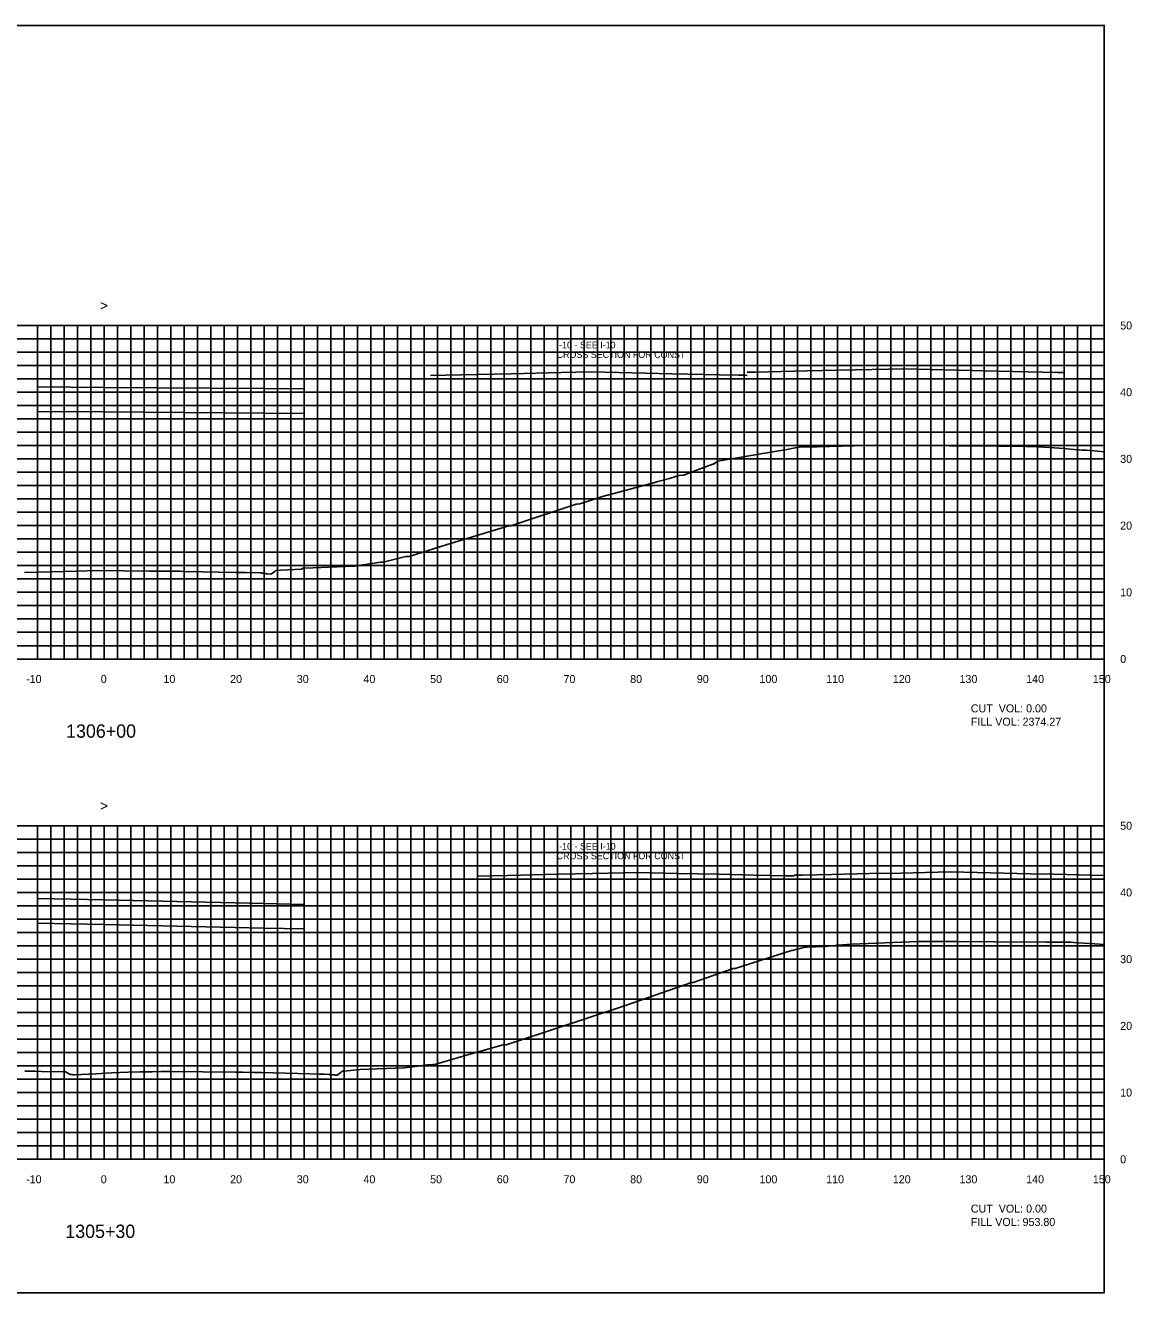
# Model space of a CAD drawing. Extents: x 1797714 to 1804825, y 249015 to 250269.
# Drawn here: x 1804319.2 to 1804485.1, y 250079.4 to 250269.4 of the extents above; entities that cross this region are included whole.
import ezdxf

# ---------------------------------------------------------------- set-up
doc = ezdxf.new("R2010")
doc.units = 0
for name, color, linetype in [('1', 7, 'Continuous'), ('10', 7, 'Continuous'), ('3', 7, 'Continuous'), ('31', 7, 'Continuous'), ('60', 7, 'Continuous'), ('ANNO-TXT', 7, 'Continuous'), ('BRG-DECK', 7, 'Continuous'), ('CL-CNST', 7, 'Continuous'), ('Level 62', 7, 'Continuous'), ('M-ROADS', 7, 'Continuous')]:
    doc.layers.add(name, color=color, linetype=linetype)

msp = doc.modelspace()

# ---------------------------------------------------------------- linework, layer by layer
msp.add_lwpolyline([(1804181, 250079.43), (1804481, 250079.43), (1804481, 250269.43), (1804181, 250269.43)], close=True)
at = {"layer": '60'}
for p, q in [((1804481, 250174.43), (1804481, 250224.43)), ((1804481.06, 250224.43), (1804481, 250224.43)), ((1804481.06, 250214.43), (1804481, 250214.43)), ((1804481.06, 250204.43), (1804481, 250204.43)), ((1804481.06, 250194.43), (1804481, 250194.43)), ((1804481.06, 250184.43), (1804481, 250184.43)), ((1804181, 250174.43), (1804481, 250174.43)), ((1804321, 250174.37), (1804321, 250174.43)), ((1804331, 250174.37), (1804331, 250174.43)), ((1804341, 250174.37), (1804341, 250174.43)), ((1804351, 250174.37), (1804351, 250174.43)), ((1804361, 250174.37), (1804361, 250174.43)), ((1804371, 250174.37), (1804371, 250174.43)), ((1804381, 250174.37), (1804381, 250174.43)), ((1804391, 250174.37), (1804391, 250174.43)), ((1804401, 250174.37), (1804401, 250174.43)), ((1804411, 250174.37), (1804411, 250174.43)), ((1804421, 250174.37), (1804421, 250174.43)), ((1804431, 250174.37), (1804431, 250174.43)), ((1804441, 250174.37), (1804441, 250174.43)), ((1804451, 250174.37), (1804451, 250174.43)), ((1804461, 250174.37), (1804461, 250174.43)), ((1804471, 250174.37), (1804471, 250174.43)), ((1804481, 250174.37), (1804481, 250174.43)), ((1804481.06, 250174.43), (1804481, 250174.43)), ((1804481, 250099.43), (1804481, 250149.43)), ((1804481.06, 250149.43), (1804481, 250149.43)), ((1804481.06, 250139.43), (1804481, 250139.43)), ((1804481.06, 250129.43), (1804481, 250129.43)), ((1804481.06, 250119.43), (1804481, 250119.43)), ((1804481.06, 250109.43), (1804481, 250109.43)), ((1804181, 250099.43), (1804481, 250099.43)), ((1804321, 250099.37), (1804321, 250099.43)), ((1804331, 250099.37), (1804331, 250099.43)), ((1804341, 250099.37), (1804341, 250099.43)), ((1804351, 250099.37), (1804351, 250099.43)), ((1804361, 250099.37), (1804361, 250099.43)), ((1804371, 250099.37), (1804371, 250099.43)), ((1804381, 250099.37), (1804381, 250099.43)), ((1804391, 250099.37), (1804391, 250099.43)), ((1804401, 250099.37), (1804401, 250099.43)), ((1804411, 250099.37), (1804411, 250099.43)), ((1804421, 250099.37), (1804421, 250099.43)), ((1804431, 250099.37), (1804431, 250099.43)), ((1804441, 250099.37), (1804441, 250099.43)), ((1804451, 250099.37), (1804451, 250099.43)), ((1804461, 250099.37), (1804461, 250099.43)), ((1804471, 250099.37), (1804471, 250099.43)), ((1804481, 250099.37), (1804481, 250099.43)), ((1804481.06, 250099.43), (1804481, 250099.43))]:
    msp.add_line(p, q, dxfattribs=at)
at = {"layer": 'BRG-DECK'}
for points in [[(1804361, 250211.25), (1804361, 250214.93), (1804355, 250214.97), (1804331, 250215.16), (1804321, 250215.23), (1804321, 250211.55), (1804331, 250211.48), (1804355, 250211.29)], [(1804361, 250133.97), (1804361, 250137.65), (1804355, 250137.78), (1804331, 250138.31), (1804321, 250138.53), (1804321, 250134.85), (1804331, 250134.63), (1804355, 250134.1)]]:
    msp.add_lwpolyline(points, close=True, dxfattribs=at)
at = {"layer": 'CL-CNST'}
for points in [[(1804379.96, 250216.94), (1804386.86, 250217.09), (1804392.02, 250217.21), (1804399.53, 250217.37), (1804404.08, 250217.47), (1804412.21, 250217.29), (1804416.15, 250217.21), (1804423.37, 250217.05), (1804426.2, 250216.99), (1804427.11, 250216.97), (1804427.45, 250216.96)], [(1804427.45, 250217.43), (1804427.78, 250217.44), (1804428.71, 250217.45), (1804436.46, 250217.62), (1804438.76, 250217.67), (1804448.65, 250217.88), (1804450.82, 250217.93), (1804461.32, 250217.69), (1804462.88, 250217.65), (1804474, 250217.4), (1804474.94, 250217.38)], [(1804321, 250215.23), (1804331, 250215.16), (1804355, 250214.97), (1804361, 250214.93)], [(1804387.03, 250141.89), (1804391.57, 250141.99), (1804399.09, 250142.15), (1804404.24, 250142.26), (1804411.15, 250142.41), (1804416.92, 250142.29), (1804423.21, 250142.15), (1804428.49, 250142.03), (1804433.26, 250141.92), (1804433.95, 250141.91), (1804434.51, 250141.9)], [(1804434.52, 250142), (1804435.08, 250142.02), (1804435.77, 250142.03), (1804440.08, 250142.12), (1804445.82, 250142.25), (1804450.49, 250142.34), (1804457.89, 250142.5), (1804461.99, 250142.41), (1804469.95, 250142.23), (1804473.5, 250142.15), (1804481, 250141.98)], [(1804321, 250138.53), (1804331, 250138.31), (1804355, 250137.78), (1804361, 250137.65)]]:
    msp.add_lwpolyline(points, dxfattribs=at)
at = {"layer": 'Level 62'}
for p, q in [((1804181, 250224.43), (1804481, 250224.43)), ((1804321, 250174.43), (1804321, 250224.43)), ((1804323, 250174.43), (1804323, 250224.43)), ((1804325, 250174.43), (1804325, 250224.43)), ((1804327, 250174.43), (1804327, 250224.43)), ((1804329, 250174.43), (1804329, 250224.43)), ((1804331, 250174.43), (1804331, 250224.43)), ((1804333, 250174.43), (1804333, 250224.43)), ((1804335, 250174.43), (1804335, 250224.43)), ((1804337, 250174.43), (1804337, 250224.43)), ((1804339, 250174.43), (1804339, 250224.43)), ((1804341, 250174.43), (1804341, 250224.43)), ((1804343, 250174.43), (1804343, 250224.43)), ((1804345, 250174.43), (1804345, 250224.43)), ((1804347, 250174.43), (1804347, 250224.43)), ((1804349, 250174.43), (1804349, 250224.43)), ((1804351, 250174.43), (1804351, 250224.43)), ((1804353, 250174.43), (1804353, 250224.43)), ((1804355, 250174.43), (1804355, 250224.43)), ((1804357, 250174.43), (1804357, 250224.43)), ((1804359, 250174.43), (1804359, 250224.43)), ((1804361, 250174.43), (1804361, 250224.43)), ((1804363, 250174.43), (1804363, 250224.43)), ((1804365, 250174.43), (1804365, 250224.43)), ((1804367, 250174.43), (1804367, 250224.43)), ((1804369, 250174.43), (1804369, 250224.43)), ((1804371, 250174.43), (1804371, 250224.43)), ((1804373, 250174.43), (1804373, 250224.43)), ((1804375, 250174.43), (1804375, 250224.43)), ((1804377, 250174.43), (1804377, 250224.43)), ((1804379, 250174.43), (1804379, 250224.43)), ((1804381, 250174.43), (1804381, 250224.43)), ((1804383, 250174.43), (1804383, 250224.43)), ((1804385, 250174.43), (1804385, 250224.43)), ((1804387, 250174.43), (1804387, 250224.43)), ((1804389, 250174.43), (1804389, 250224.43)), ((1804391, 250174.43), (1804391, 250224.43)), ((1804393, 250174.43), (1804393, 250224.43)), ((1804395, 250174.43), (1804395, 250224.43)), ((1804397, 250174.43), (1804397, 250224.43)), ((1804399, 250174.43), (1804399, 250224.43)), ((1804401, 250174.43), (1804401, 250224.43)), ((1804403, 250174.43), (1804403, 250224.43)), ((1804405, 250174.43), (1804405, 250224.43)), ((1804407, 250174.43), (1804407, 250224.43)), ((1804409, 250174.43), (1804409, 250224.43)), ((1804411, 250174.43), (1804411, 250224.43)), ((1804413, 250174.43), (1804413, 250224.43)), ((1804415, 250174.43), (1804415, 250224.43)), ((1804417, 250174.43), (1804417, 250224.43)), ((1804419, 250174.43), (1804419, 250224.43)), ((1804421, 250174.43), (1804421, 250224.43)), ((1804423, 250174.43), (1804423, 250224.43)), ((1804425, 250174.43), (1804425, 250224.43)), ((1804427, 250174.43), (1804427, 250224.43)), ((1804429, 250174.43), (1804429, 250224.43)), ((1804431, 250174.43), (1804431, 250224.43)), ((1804433, 250174.43), (1804433, 250224.43)), ((1804435, 250174.43), (1804435, 250224.43)), ((1804437, 250174.43), (1804437, 250224.43)), ((1804439, 250174.43), (1804439, 250224.43)), ((1804441, 250174.43), (1804441, 250224.43)), ((1804443, 250174.43), (1804443, 250224.43)), ((1804445, 250174.43), (1804445, 250224.43)), ((1804447, 250174.43), (1804447, 250224.43)), ((1804449, 250174.43), (1804449, 250224.43)), ((1804451, 250174.43), (1804451, 250224.43)), ((1804453, 250174.43), (1804453, 250224.43)), ((1804455, 250174.43), (1804455, 250224.43)), ((1804457, 250174.43), (1804457, 250224.43)), ((1804459, 250174.43), (1804459, 250224.43)), ((1804461, 250174.43), (1804461, 250224.43)), ((1804463, 250174.43), (1804463, 250224.43)), ((1804465, 250174.43), (1804465, 250224.43)), ((1804467, 250174.43), (1804467, 250224.43)), ((1804469, 250174.43), (1804469, 250224.43)), ((1804471, 250174.43), (1804471, 250224.43)), ((1804473, 250174.43), (1804473, 250224.43)), ((1804475, 250174.43), (1804475, 250224.43)), ((1804477, 250174.43), (1804477, 250224.43)), ((1804479, 250174.43), (1804479, 250224.43)), ((1804481, 250174.43), (1804481, 250224.43)), ((1804181, 250222.43), (1804481, 250222.43)), ((1804181, 250220.43), (1804481, 250220.43)), ((1804181, 250218.43), (1804481, 250218.43)), ((1804181, 250216.43), (1804481, 250216.43)), ((1804181, 250214.43), (1804481, 250214.43)), ((1804181, 250212.43), (1804481, 250212.43)), ((1804181, 250210.43), (1804481, 250210.43)), ((1804181, 250208.43), (1804481, 250208.43)), ((1804181, 250206.43), (1804481, 250206.43)), ((1804181, 250204.43), (1804481, 250204.43)), ((1804181, 250202.43), (1804481, 250202.43)), ((1804181, 250200.43), (1804481, 250200.43)), ((1804181, 250198.43), (1804481, 250198.43)), ((1804181, 250196.43), (1804481, 250196.43)), ((1804181, 250194.43), (1804481, 250194.43)), ((1804181, 250192.43), (1804481, 250192.43)), ((1804181, 250190.43), (1804481, 250190.43)), ((1804181, 250188.43), (1804481, 250188.43)), ((1804181, 250186.43), (1804481, 250186.43)), ((1804181, 250184.43), (1804481, 250184.43)), ((1804181, 250182.43), (1804481, 250182.43)), ((1804181, 250180.43), (1804481, 250180.43)), ((1804181, 250178.43), (1804481, 250178.43)), ((1804181, 250176.43), (1804481, 250176.43)), ((1804181, 250174.43), (1804481, 250174.43)), ((1804181, 250149.43), (1804481, 250149.43)), ((1804321, 250099.43), (1804321, 250149.43)), ((1804323, 250099.43), (1804323, 250149.43)), ((1804325, 250099.43), (1804325, 250149.43)), ((1804327, 250099.43), (1804327, 250149.43)), ((1804329, 250099.43), (1804329, 250149.43)), ((1804331, 250099.43), (1804331, 250149.43)), ((1804333, 250099.43), (1804333, 250149.43)), ((1804335, 250099.43), (1804335, 250149.43)), ((1804337, 250099.43), (1804337, 250149.43)), ((1804339, 250099.43), (1804339, 250149.43)), ((1804341, 250099.43), (1804341, 250149.43)), ((1804343, 250099.43), (1804343, 250149.43)), ((1804345, 250099.43), (1804345, 250149.43)), ((1804347, 250099.43), (1804347, 250149.43)), ((1804349, 250099.43), (1804349, 250149.43)), ((1804351, 250099.43), (1804351, 250149.43)), ((1804353, 250099.43), (1804353, 250149.43)), ((1804355, 250099.43), (1804355, 250149.43)), ((1804357, 250099.43), (1804357, 250149.43)), ((1804359, 250099.43), (1804359, 250149.43)), ((1804361, 250099.43), (1804361, 250149.43)), ((1804363, 250099.43), (1804363, 250149.43)), ((1804365, 250099.43), (1804365, 250149.43)), ((1804367, 250099.43), (1804367, 250149.43)), ((1804369, 250099.43), (1804369, 250149.43)), ((1804371, 250099.43), (1804371, 250149.43)), ((1804373, 250099.43), (1804373, 250149.43)), ((1804375, 250099.43), (1804375, 250149.43)), ((1804377, 250099.43), (1804377, 250149.43)), ((1804379, 250099.43), (1804379, 250149.43)), ((1804381, 250099.43), (1804381, 250149.43)), ((1804383, 250099.43), (1804383, 250149.43)), ((1804385, 250099.43), (1804385, 250149.43)), ((1804387, 250099.43), (1804387, 250149.43)), ((1804389, 250099.43), (1804389, 250149.43)), ((1804391, 250099.43), (1804391, 250149.43)), ((1804393, 250099.43), (1804393, 250149.43)), ((1804395, 250099.43), (1804395, 250149.43)), ((1804397, 250099.43), (1804397, 250149.43)), ((1804399, 250099.43), (1804399, 250149.43)), ((1804401, 250099.43), (1804401, 250149.43)), ((1804403, 250099.43), (1804403, 250149.43)), ((1804405, 250099.43), (1804405, 250149.43)), ((1804407, 250099.43), (1804407, 250149.43)), ((1804409, 250099.43), (1804409, 250149.43)), ((1804411, 250099.43), (1804411, 250149.43)), ((1804413, 250099.43), (1804413, 250149.43)), ((1804415, 250099.43), (1804415, 250149.43)), ((1804417, 250099.43), (1804417, 250149.43)), ((1804419, 250099.43), (1804419, 250149.43)), ((1804421, 250099.43), (1804421, 250149.43)), ((1804423, 250099.43), (1804423, 250149.43)), ((1804425, 250099.43), (1804425, 250149.43)), ((1804427, 250099.43), (1804427, 250149.43)), ((1804429, 250099.43), (1804429, 250149.43)), ((1804431, 250099.43), (1804431, 250149.43)), ((1804433, 250099.43), (1804433, 250149.43)), ((1804435, 250099.43), (1804435, 250149.43)), ((1804437, 250099.43), (1804437, 250149.43)), ((1804439, 250099.43), (1804439, 250149.43)), ((1804441, 250099.43), (1804441, 250149.43)), ((1804443, 250099.43), (1804443, 250149.43)), ((1804445, 250099.43), (1804445, 250149.43)), ((1804447, 250099.43), (1804447, 250149.43)), ((1804449, 250099.43), (1804449, 250149.43)), ((1804451, 250099.43), (1804451, 250149.43)), ((1804453, 250099.43), (1804453, 250149.43)), ((1804455, 250099.43), (1804455, 250149.43)), ((1804457, 250099.43), (1804457, 250149.43)), ((1804459, 250099.43), (1804459, 250149.43)), ((1804461, 250099.43), (1804461, 250149.43)), ((1804463, 250099.43), (1804463, 250149.43)), ((1804465, 250099.43), (1804465, 250149.43)), ((1804467, 250099.43), (1804467, 250149.43)), ((1804469, 250099.43), (1804469, 250149.43)), ((1804471, 250099.43), (1804471, 250149.43)), ((1804473, 250099.43), (1804473, 250149.43)), ((1804475, 250099.43), (1804475, 250149.43)), ((1804477, 250099.43), (1804477, 250149.43)), ((1804479, 250099.43), (1804479, 250149.43)), ((1804481, 250099.43), (1804481, 250149.43)), ((1804181, 250147.43), (1804481, 250147.43)), ((1804181, 250145.43), (1804481, 250145.43)), ((1804181, 250143.43), (1804481, 250143.43)), ((1804181, 250141.43), (1804481, 250141.43)), ((1804181, 250139.43), (1804481, 250139.43)), ((1804181, 250137.43), (1804481, 250137.43)), ((1804181, 250135.43), (1804481, 250135.43)), ((1804181, 250133.43), (1804481, 250133.43)), ((1804181, 250131.43), (1804481, 250131.43)), ((1804181, 250129.43), (1804481, 250129.43)), ((1804181, 250127.43), (1804481, 250127.43)), ((1804181, 250125.43), (1804481, 250125.43)), ((1804181, 250123.43), (1804481, 250123.43)), ((1804181, 250121.43), (1804481, 250121.43)), ((1804181, 250119.43), (1804481, 250119.43)), ((1804181, 250117.43), (1804481, 250117.43)), ((1804181, 250115.43), (1804481, 250115.43)), ((1804181, 250113.43), (1804481, 250113.43)), ((1804181, 250111.43), (1804481, 250111.43)), ((1804181, 250109.43), (1804481, 250109.43)), ((1804181, 250107.43), (1804481, 250107.43)), ((1804181, 250105.43), (1804481, 250105.43)), ((1804181, 250103.43), (1804481, 250103.43)), ((1804181, 250101.43), (1804481, 250101.43)), ((1804181, 250099.43), (1804481, 250099.43))]:
    msp.add_line(p, q, dxfattribs=at)
at = {"layer": 'M-ROADS'}
for points in [[(1804319.06, 250187.39), (1804326.79, 250187.61), (1804330.05, 250187.68), (1804337.84, 250187.61), (1804342.37, 250187.58), (1804343.18, 250187.56), (1804350.75, 250187.41), (1804352.31, 250187.38), (1804354.48, 250187.34), (1804354.54, 250187.33), (1804354.73, 250187.3), (1804354.88, 250187.28), (1804355, 250187.26), (1804355.09, 250187.25), (1804355.17, 250187.24), (1804355.23, 250187.23), (1804355.29, 250187.22), (1804355.33, 250187.21), (1804355.37, 250187.21), (1804355.41, 250187.2), (1804355.44, 250187.2), (1804355.47, 250187.19), (1804355.49, 250187.19), (1804355.51, 250187.19), (1804356.02, 250187.13), (1804356.11, 250187.19), (1804356.66, 250187.58), (1804356.78, 250187.68), (1804357.45, 250187.75), (1804360.59, 250187.9), (1804360.86, 250188.03), (1804361.12, 250188.03), (1804368.44, 250188.34), (1804368.57, 250188.34), (1804372.49, 250188.93), (1804372.84, 250188.94), (1804376.27, 250189.82), (1804376.47, 250189.82), (1804376.77, 250189.82), (1804382.47, 250191.59), (1804391.72, 250194.4), (1804392.02, 250194.39), (1804401.8, 250197.66), (1804401.91, 250197.67), (1804402.37, 250197.69), (1804405.77, 250198.78), (1804413.6, 250200.91), (1804414.05, 250201.03), (1804415.82, 250201.51), (1804416.76, 250201.79), (1804417.05, 250201.89), (1804417.24, 250201.93), (1804417.94, 250202.01), (1804418.67, 250202.27), (1804422.28, 250203.62), (1804422.41, 250203.62), (1804423.05, 250204.1), (1804429.78, 250205.25), (1804433.41, 250205.86), (1804434.66, 250206.11), (1804435.56, 250206.22), (1804436.88, 250206.23), (1804437.8, 250206.24), (1804438.01, 250206.24), (1804445.34, 250206.45), (1804446.66, 250206.5), (1804455.4, 250206.43), (1804457.73, 250206.41), (1804460.98, 250206.38), (1804469.3, 250206.31), (1804470.24, 250206.27), (1804472.81, 250206.14), (1804474.24, 250206.02), (1804474.96, 250205.97), (1804477.01, 250205.81), (1804477.23, 250205.79), (1804477.68, 250205.76), (1804477.87, 250205.75), (1804478.23, 250205.76), (1804478.27, 250205.75), (1804478.37, 250205.74), (1804480.03, 250205.58), (1804481, 250205.47)], [(1804319.11, 250112.66), (1804319.51, 250112.66), (1804320.59, 250112.64), (1804320.64, 250112.64), (1804321.61, 250112.6), (1804325.22, 250112.56), (1804325.45, 250112.39), (1804325.89, 250112.12), (1804326.28, 250112.12), (1804326.31, 250112.11), (1804326.34, 250112.11), (1804326.37, 250112.11), (1804326.41, 250112.11), (1804326.46, 250112.1), (1804326.52, 250112.1), (1804326.55, 250112.1), (1804329.74, 250112.26), (1804332.09, 250112.38), (1804334.57, 250112.51), (1804336.34, 250112.55), (1804336.83, 250112.55), (1804337.08, 250112.55), (1804337.13, 250112.55), (1804338.21, 250112.56), (1804339.57, 250112.57), (1804340.85, 250112.57), (1804350.67, 250112.51), (1804351.83, 250112.5), (1804353.4, 250112.46), (1804354.59, 250112.43), (1804361.85, 250112.25), (1804363.29, 250112.21), (1804363.94, 250112.2), (1804364.01, 250112.19), (1804364.66, 250112.14), (1804364.99, 250112.12), (1804365.18, 250112.1), (1804365.31, 250112.09), (1804365.41, 250112.08), (1804365.48, 250112.08), (1804365.53, 250112.07), (1804365.58, 250112.07), (1804365.59, 250112.07), (1804365.61, 250112.07), (1804365.65, 250112.06), (1804365.67, 250112.06), (1804365.69, 250112.06), (1804365.71, 250112.06), (1804365.73, 250112.05), (1804365.75, 250112.05), (1804365.76, 250112.05), (1804365.77, 250112.05), (1804365.78, 250112.05), (1804365.79, 250112.05), (1804365.8, 250112.05), (1804365.81, 250112.05), (1804365.96, 250112.03), (1804366.54, 250112.48), (1804366.57, 250112.5), (1804366.61, 250112.53), (1804366.71, 250112.62), (1804366.74, 250112.62), (1804366.96, 250112.62), (1804369.41, 250112.87), (1804375.94, 250113.14), (1804376.01, 250113.14), (1804377.19, 250113.27), (1804377.3, 250113.29), (1804379.84, 250113.63), (1804380.2, 250113.61), (1804380.37, 250113.63), (1804380.44, 250113.63), (1804380.75, 250113.69), (1804385.69, 250115.14), (1804390.84, 250116.6), (1804390.89, 250116.6), (1804391.33, 250116.6), (1804392.65, 250117.04), (1804392.72, 250117.05), (1804409.03, 250122.45), (1804419.1, 250125.92), (1804419.33, 250125.94), (1804425.33, 250128.03), (1804425.63, 250128.02), (1804434.08, 250130.74), (1804434.21, 250130.74), (1804436.09, 250131.21), (1804436.44, 250131.21), (1804439.22, 250131.34), (1804441.08, 250131.51), (1804443.09, 250131.69), (1804448.03, 250131.88), (1804453.15, 250132.07), (1804455.58, 250132.07), (1804458.83, 250132.06), (1804464.55, 250132.05), (1804472.31, 250132), (1804476.01, 250131.97), (1804476.44, 250131.94), (1804479.52, 250131.73), (1804479.59, 250131.73), (1804481, 250131.61)]]:
    msp.add_lwpolyline(points, dxfattribs=at)

# ---------------------------------------------------------------- texts
at = {"layer": '1'}
for s, p in [('1306+00', (1804325.3, 250162.63)), ('1305+30', (1804325.18, 250087.63))]:
    msp.add_text(s, height=2, dxfattribs=at).set_placement(p)
at = {"layer": '10'}
for s, p in [('-10', (1804319.3, 250170.83)), ('0', (1804330.5, 250170.83)), ('10', (1804339.9, 250170.83)), ('20', (1804349.9, 250170.83)), ('30', (1804359.9, 250170.83)), ('40', (1804369.9, 250170.83)), ('50', (1804379.9, 250170.83)), ('60', (1804389.9, 250170.83)), ('70', (1804399.9, 250170.83)), ('80', (1804409.9, 250170.83)), ('90', (1804419.9, 250170.83)), ('100', (1804429.3, 250170.83)), ('110', (1804439.3, 250170.83)), ('120', (1804449.3, 250170.83)), ('130', (1804459.3, 250170.83)), ('140', (1804469.3, 250170.83)), ('150', (1804479.3, 250170.83)), ('-10', (1804319.3, 250095.83)), ('0', (1804330.5, 250095.83)), ('10', (1804339.9, 250095.83)), ('20', (1804349.9, 250095.83)), ('30', (1804359.9, 250095.83)), ('40', (1804369.9, 250095.83)), ('50', (1804379.9, 250095.83)), ('60', (1804389.9, 250095.83)), ('70', (1804399.9, 250095.83)), ('80', (1804409.9, 250095.83)), ('90', (1804419.9, 250095.83)), ('100', (1804429.3, 250095.83)), ('110', (1804439.3, 250095.83)), ('120', (1804449.3, 250095.83)), ('130', (1804459.3, 250095.83)), ('140', (1804469.3, 250095.83)), ('150', (1804479.3, 250095.83))]:
    msp.add_text(s, height=1.2, dxfattribs=at).set_placement(p)
at = {"layer": '3'}
for s, p in [('CROSS SECTION FOR CONST ', (1804398.87, 250219.57)), ('I-10 - SEE I-10 ', (1804398.87, 250221.01)), ('I-10 - SEE I-10 ', (1804398.88, 250145.85)), ('CROSS SECTION FOR CONST ', (1804398.88, 250144.41))]:
    msp.add_text(s, height=1, dxfattribs=at).set_placement(p)
at = {"layer": '31'}
for s, p in [('50', (1804483.4, 250223.83)), ('40', (1804483.4, 250213.83)), ('30', (1804483.4, 250203.83)), ('20', (1804483.4, 250193.83)), ('10', (1804483.4, 250183.83)), ('0', (1804483.4, 250173.83)), ('50', (1804483.4, 250148.83)), ('40', (1804483.4, 250138.83)), ('30', (1804483.4, 250128.83)), ('20', (1804483.4, 250118.83)), ('10', (1804483.4, 250108.83)), ('0', (1804483.4, 250098.83))]:
    msp.add_text(s, height=1.2, dxfattribs=at).set_placement(p)
at = {"layer": '60'}
for p in [(1804330.39, 250226.68), (1804330.39, 250151.68)]:
    msp.add_text('>', height=1.5, dxfattribs=at).set_placement(p)
at = {"layer": 'ANNO-TXT'}
for s, p in [('CUT  VOL: 0.00', (1804461, 250166.43)), ('FILL VOL: 2374.27', (1804461, 250164.43)), ('CUT  VOL: 0.00', (1804461, 250091.43)), ('FILL VOL: 953.80', (1804461, 250089.43))]:
    msp.add_text(s, height=1.2, dxfattribs=at).set_placement(p)

doc.saveas('drawing.dxf')
